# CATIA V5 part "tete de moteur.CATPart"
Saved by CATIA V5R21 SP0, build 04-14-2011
Part number: tete de moteur
Material "Aluminium": density 2710 kg/m3, Young's modulus 7e+10 Pa, Poisson ratio 0.346, thermal expansion 2.36e-05 1/K
Bounding box of the stored display mesh (mm): x -16.989 to 17.003, y -17.05 to 17.05, z 0 to 13.5
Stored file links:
  C:\Users\Olivier\Desktop\redaction CATIA (local)\CATIA\DONNEES\Exercice assemblage 3 (Pompe de ventilation)\Assemblage ensemble bloc moteur (Product inclus)\tete de moteur.CATPart
  C:\Users\Olivier\Desktop\redaction TBM CATIA\pompe à moteur de ventilation refait\engine block.CATPart
  C:\Program Files\Dassault Systemes\B21\win_b64\startup\materials\French\Catalog.CATMaterial
  C:\Program Files\Dassault Systemes\B21\win_b64\resources\graphic\figures\CATIA_EnvironmentMap_Hall_512x512.jpg
  C:\Users\Olivier\Desktop\redaction CATIA (local)\CATIA\DONNEES\Exercice assemblage 3 (Pompe de ventilation)\Assemblage ensemble bloc moteur (Product inclus)\CATIA_EnvironmentMap_DSBlack_512x512.jpg
  C:\Program Files\Dassault Systemes\B21\win_b64\resources\graphic\figures\CATIA_EnvironmentMap_GridSpot_512x512.jpg
  C:\Program Files\Dassault Systemes\B21\win_b64\resources\graphic\figures\CATIA_EnvironmentMap_NonLinear_512x512.jpg
  C:\Program Files\Dassault Systemes\B21\win_b64\resources\graphic\figures\CATIA_EnvironmentMap_Square2_512x512.jpg
  C:\Users\Olivier\Desktop\redaction CATIA (local)\pompe à moteur de ventilation refait\Pompe_a_moteur_de_ventilation.CATProduct
  C:\Users\Olivier\Desktop\redaction CATIA (local)\pompe à moteur de ventilation refait\Ecrou a collerette M5.CATPart
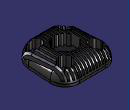
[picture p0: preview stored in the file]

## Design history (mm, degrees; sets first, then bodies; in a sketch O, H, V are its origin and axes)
Body1 (main body), material "Aluminium"
  Sketch1 on xy-plane, origin (0, 0, 0), H (1, 0, 0), V (0, 1, 0)
    point P1 (0, 0)
    point P2 (0, 1.25)
    point P3 (0, -12.5)
    arc A1 centre (-8.2069, 8.2501) radius 8.7999 from (-8.2068, 17.05) to (-16.9887, 7.686) ccw
    line L1 (-16.9887, 7.686) -> (-16.0612, -6.755)
    arc A2 centre (-5.0839, -6.0501) radius 10.9999 from (-16.0612, -6.755) to (-5.0838, -17.05) ccw
    line L2 (-5.0838, -17.05) -> (5.0898, -17.05)
    arc A3 centre (5.0899, -6.0501) radius 10.9999 from (5.0898, -17.05) to (16.0668, -6.7614) ccw
    line L3 (16.0668, -6.7614) -> (17.0027, 7.6809)
    arc A4 centre (8.2212, 8.2501) radius 8.7999 from (17.0027, 7.6809) to (8.2211, 17.05) ccw
    line L4 (8.2211, 17.05) -> (-8.2068, 17.05)
    distance L4 L2 = 34.1
    distance L4 H = 17.05
  Pad1: profile Sketch1, direction (0, 0, 1), length 13.5
  Fillet1: radius 8, on edge [face of Pad1 from Sketch1.L1 | end face of Pad1]
  Sketch2 on zx-plane, origin (0, 0, 0), H (-1, 0, 0), V (0, 0, 1)
    line L1 (0.5, 15.593) -> (0.5, 6.7271)
    point P1 (0.5, 6.7271)
    point P2 (1.5, 6.7271)
    line L2 (1.5, 15.593) -> (1.5, 6.7271)
    line L3 (0.5, 6.7271) -> (1.5, 6.7271)
    line L4 (0.5, 15.593) -> (1.5, 15.593)
    point P5 (1.5, 15.593)
    point P6 (0.5, 15.593)
    point P7 (2.5, 6.7271)
    point P8 (3.5, 6.7271)
    point P9 (3.5, 15.593)
    point P10 (2.5, 15.593)
    line L5 (2.5, 15.593) -> (2.5, 6.7271)
    line L6 (3.5, 15.593) -> (3.5, 6.7271)
    line L7 (2.5, 6.7271) -> (3.5, 6.7271)
    line L8 (2.5, 15.593) -> (3.5, 15.593)
    point P11 (4.5, 6.7271)
    point P12 (5.5, 6.7271)
    point P13 (5.5, 15.593)
    point P14 (4.5, 15.593)
    line L9 (4.5, 15.593) -> (4.5, 6.7271)
    line L10 (5.5, 15.593) -> (5.5, 6.7271)
    line L11 (4.5, 6.7271) -> (5.5, 6.7271)
    line L12 (4.5, 15.593) -> (5.5, 15.593)
    point P15 (6.5, 6.7271)
    point P16 (7.5, 6.7271)
    point P17 (7.5, 15.593)
    point P18 (6.5, 15.593)
    line L13 (6.5, 15.593) -> (6.5, 6.7271)
    line L14 (7.5, 15.593) -> (7.5, 6.7271)
    line L15 (6.5, 6.7271) -> (7.5, 6.7271)
    line L16 (6.5, 15.593) -> (7.5, 15.593)
    point P19 (8.5, 6.7271)
    point P20 (9.5, 6.7271)
    point P21 (9.5, 15.593)
    point P22 (8.5, 15.593)
    line L17 (8.5, 15.593) -> (8.5, 6.7271)
    line L18 (9.5, 15.593) -> (9.5, 6.7271)
    line L19 (8.5, 6.7271) -> (9.5, 6.7271)
    line L20 (8.5, 15.593) -> (9.5, 15.593)
    point P23 (10.5, 6.7271)
    point P24 (11.5, 6.7271)
    point P25 (11.5, 15.593)
    point P26 (10.5, 15.593)
    line L21 (10.5, 15.593) -> (10.5, 6.7271)
    line L22 (11.5, 15.593) -> (11.5, 6.7271)
    line L23 (10.5, 6.7271) -> (11.5, 6.7271)
    line L24 (10.5, 15.593) -> (11.5, 15.593)
    point P27 (12.5, 6.7271)
    point P28 (13.5, 6.7271)
    point P29 (13.5, 15.593)
    point P30 (12.5, 15.593)
    line L25 (12.5, 15.593) -> (12.5, 6.7271)
    line L26 (13.5, 15.593) -> (13.5, 6.7271)
    line L27 (12.5, 6.7271) -> (13.5, 6.7271)
    line L28 (12.5, 15.593) -> (13.5, 15.593)
    point P31 (14.5, 6.7271)
    point P32 (15.5, 6.7271)
    point P33 (15.5, 15.593)
    point P34 (14.5, 15.593)
    line L29 (14.5, 15.593) -> (14.5, 6.7271)
    line L30 (15.5, 15.593) -> (15.5, 6.7271)
    line L31 (14.5, 6.7271) -> (15.5, 6.7271)
    line L32 (14.5, 15.593) -> (15.5, 15.593)
    point P35 (-0.5, 6.7271)
    point P36 (-1.5, 6.7271)
    point P37 (-1.5, 15.593)
    point P38 (-0.5, 15.593)
    point P39 (-2.5, 6.7271)
    point P40 (-3.5, 6.7271)
    point P41 (-3.5, 15.593)
    point P42 (-2.5, 15.593)
    point P43 (-4.5, 6.7271)
    point P44 (-5.5, 6.7271)
    point P45 (-5.5, 15.593)
    point P46 (-4.5, 15.593)
    point P47 (-6.5, 6.7271)
    point P48 (-7.5, 6.7271)
    point P49 (-7.5, 15.593)
    point P50 (-6.5, 15.593)
    point P51 (-8.5, 6.7271)
    point P52 (-9.5, 6.7271)
    point P53 (-9.5, 15.593)
    point P54 (-8.5, 15.593)
    point P55 (-10.5, 6.7271)
    point P56 (-11.5, 6.7271)
    point P57 (-11.5, 15.593)
    point P58 (-10.5, 15.593)
    point P59 (-12.5, 6.7271)
    point P60 (-13.5, 6.7271)
    point P61 (-13.5, 15.593)
    point P62 (-12.5, 15.593)
    point P63 (-14.5, 6.7271)
    point P64 (-15.5, 6.7271)
    point P65 (-15.5, 15.593)
    point P66 (-14.5, 15.593)
    line L33 (-0.5, 15.593) -> (-0.5, 6.7271)
    line L34 (-1.5, 15.593) -> (-1.5, 6.7271)
    line L35 (-0.5, 6.7271) -> (-1.5, 6.7271)
    line L36 (-0.5, 15.593) -> (-1.5, 15.593)
    line L37 (-2.5, 15.593) -> (-2.5, 6.7271)
    line L38 (-3.5, 15.593) -> (-3.5, 6.7271)
    line L39 (-2.5, 6.7271) -> (-3.5, 6.7271)
    line L40 (-2.5, 15.593) -> (-3.5, 15.593)
    line L41 (-4.5, 15.593) -> (-4.5, 6.7271)
    line L42 (-5.5, 15.593) -> (-5.5, 6.7271)
    line L43 (-4.5, 6.7271) -> (-5.5, 6.7271)
    line L44 (-4.5, 15.593) -> (-5.5, 15.593)
    line L45 (-6.5, 15.593) -> (-6.5, 6.7271)
    line L46 (-7.5, 15.593) -> (-7.5, 6.7271)
    line L47 (-6.5, 6.7271) -> (-7.5, 6.7271)
    line L48 (-6.5, 15.593) -> (-7.5, 15.593)
    line L49 (-8.5, 15.593) -> (-8.5, 6.7271)
    line L50 (-9.5, 15.593) -> (-9.5, 6.7271)
    line L51 (-8.5, 6.7271) -> (-9.5, 6.7271)
    line L52 (-8.5, 15.593) -> (-9.5, 15.593)
    line L53 (-10.5, 15.593) -> (-10.5, 6.7271)
    line L54 (-11.5, 15.593) -> (-11.5, 6.7271)
    line L55 (-10.5, 6.7271) -> (-11.5, 6.7271)
    line L56 (-10.5, 15.593) -> (-11.5, 15.593)
    line L57 (-12.5, 15.593) -> (-12.5, 6.7271)
    line L58 (-13.5, 15.593) -> (-13.5, 6.7271)
    line L59 (-12.5, 6.7271) -> (-13.5, 6.7271)
    line L60 (-12.5, 15.593) -> (-13.5, 15.593)
    line L61 (-14.5, 15.593) -> (-14.5, 6.7271)
    line L62 (-15.5, 15.593) -> (-15.5, 6.7271)
    line L63 (-14.5, 6.7271) -> (-15.5, 6.7271)
    line L64 (-14.5, 15.593) -> (-15.5, 15.593)
    distance L2 L1 = 1
    distance L1 V = 0.5
    vertical: L1 V
    horizontal: L3 H, L4 H
    symmetry: P1 P35 V, P2 P36 V, P5 P37 V, P6 P38 V, P7 P39 V, P8 P40 V, P9 P41 V, P10 P42 V, P11 P43 V, P12 P44 V, P13 P45 V, P14 P46 V, P15 P47 V, P16 P48 V, P17 P49 V, P18 P50 V, P19 P51 V, P20 P52 V, P21 P53 V, P22 P54 V, P23 P55 V, P24 P56 V, P25 P57 V, P26 P58 V, P27 P59 V, P28 P60 V, P29 P61 V, P30 P62 V, P31 P63 V, P32 P64 V, P33 P65 V, P34 P66 V, L1 L33 V, L2 L34 V, L3 L35 V, L4 L36 V, L5 L37 V, L6 L38 V, L7 L39 V, L8 L40 V, L9 L41 V, L10 L42 V, L11 L43 V, L12 L44 V, L13 L45 V, L14 L46 V, L15 L47 V, L16 L48 V, L17 L49 V, L18 L50 V, L19 L51 V, L20 L52 V, L21 L53 V, L22 L54 V, L23 L55 V, L24 L56 V, L25 L57 V, L26 L58 V, L27 L59 V, L28 L60 V, L29 L61 V, L30 L62 V, L31 L63 V, L32 L64 V
  Pocket1: profile Sketch2, direction (0, -1, 0), length 18.5, mirrored extent
  Sketch3 on start face of Pad1, origin (0, 0, 0), H (1, 0, 0), V (0, -1, 0)
    circle A1 centre (0, 0) radius 6.5
    circle A2 centre (0, 0) radius 3
    arc A3 centre (-7.3863, -7.4252) radius 7.9198 from (-15.2898, -6.9174) to (-7.3861, -15.345) ccw
    line L1 (-15.2898, -6.9174) -> (-14.4551, 6.0795)
    arc A4 centre (-4.5756, 5.4452) radius 9.8998 from (-4.5754, 15.345) to (-14.4551, 6.0795) ccw
    line L2 (-4.5754, 15.345) -> (4.5808, 15.345)
    arc A5 centre (4.581, 5.4452) radius 9.8998 from (14.4601, 6.0852) to (4.5808, 15.345) ccw
    line L3 (14.4601, 6.0852) -> (15.3024, -6.9128)
    arc A6 centre (7.3992, -7.4252) radius 7.9198 from (7.399, -15.345) to (15.3024, -6.9128) ccw
    line L4 (7.399, -15.345) -> (-7.3861, -15.345)
    circle A7 centre (0, 0) radius 10.5
  MultiPocket1: profile Sketch3, domains (length 3.5; length 0; length 4; length 14; length 3.5)
  Sketch4 on face of Pocket1 from Sketch2.L27, origin (0, 0, 6.7271), H (1, 0, 0), V (0, 1, 0)
    circle A1 centre (9.545, 9.545) radius 1.5
    point P1 (9.545, 9.545)
    point P2 (-9.545, 9.545)
    distance P1 V = 9.545
    distance P1 H = 9.545
    radius A1 = 1.5
  Sketch5 on face of Pocket1, origin (0, 0, 6.7271), H (1, 0, 0), V (0, 1, 0)
    circle A1 centre (0, 0) radius 7
    radius A1 = 7
  Pocket2: profile Sketch5, direction (0, 0, -1), length 0, opposite side through (limit type 3)
  Sketch6 on face of Pocket2, origin (0, 0, 6.7271), H (1, 0, 0), V (0, 1, 0)
    circle A1 centre (9.545, 9.545) radius 4
    point P1 (9.545, 9.545)
    reference projected circle E1 centre (9.545, 9.545) radius 1.5 from Sketch4.A1
    radius A1 = 4
    concentricity: P1 E1
  Pocket3: profile Sketch6, direction (0, 0, 1), through (limit type 3)
  Pocket4: profile Sketch4, direction (0, 0, -1), through (limit type 3)
  RectPattern1: of Pocket3, Pocket4, Sketch4, direction 1 instances 2, spacing 19.09, along X axis reversed, direction 2 instances 2, spacing 19.09, along Y axis reversed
